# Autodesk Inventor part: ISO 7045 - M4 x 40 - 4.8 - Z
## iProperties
Library Location: C:\Program Files\Autodesk\Inventor 6\content
Library: local
SubLibrary: ISO
Family: 15
Member: 64
Member Major Revision: 1
Member Minor Revision: 1
Comments: To add or edit properties for Autodesk Inventor files, use iProperties.
Created: 2003-05
Part Number: ISO 7045 - M4 x 40 - 4.8 - Z
Vendor: Autodesk Inc.
Document SubType Name: Modeling
Designer: Philippe
Description: Vis à tête plate à empreinte cruciforme
Standard: ISO 7045 M4 x 40 - 4.8 - Z
Alert: To add or edit properties for Autodesk Inventor files, use iProperties.
Control State: 0
Master: False
Checked Out: False
Shininess: 64.0
Length Units: 11269
Angle Units: 11279
Time Units: 11290
Mass Units: 11283
Length Display Precision: 3
Angle Display Precision: 2
Compacted: True
EGR: 1
Density: 0.0
Volumn: 0.0
Area: 0.0
PropertySet Name: Model Information
Author: Philippe
Revision Number: 1
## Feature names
1. Corps [Revolution]
2. Fente [Extrusion]
3. Coupe [Revolution]
4. Coupe en étoile [Extrusion]
5. Congé1 [Fillet]
6. Congé2 [Fillet]
7. Chanfrein1 [Chamfer]
